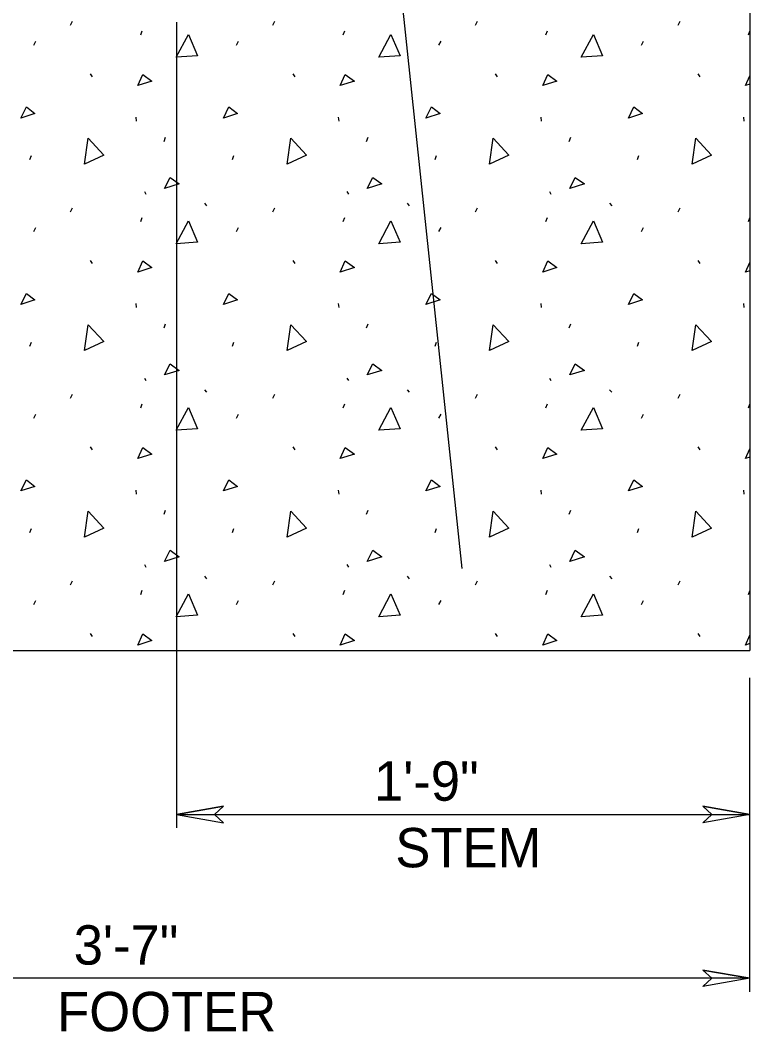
# Model space of a CAD drawing. Extents: x -26.5 to -19.2, y -3.6 to 6.6.
# Drawn here: x -23.351 to -22.237, y 0.164 to 1.707 of the extents above; entities that cross this region are included whole.
import ezdxf

# ---------------------------------------------------------------- set-up
doc = ezdxf.new("R2010")
doc.units = 0
for name, color, linetype in [('DETL-DIMS', 7, 'Continuous'), ('DETL-PATT', 7, 'Continuous'), ('Level 10', 7, 'Continuous'), ('Level 12', 7, 'Continuous'), ('SUBS-FOOT_P', 7, 'Continuous'), ('SUPR-RFRC', 7, 'Continuous')]:
    doc.layers.add(name, color=color, linetype=linetype)

msp = doc.modelspace()

# ---------------------------------------------------------------- linework, layer by layer
at = {"layer": 'DETL-DIMS'}
for p, q in [((-23.112, 0.4955), (-23.0405, 0.508)), ((-23.112, 0.4955), (-23.0405, 0.4828)), ((-23.0405, 0.508), (-23.054, 0.4955)), ((-23.054, 0.4955), (-23.0405, 0.4828)), ((-22.237, 0.4955), (-22.3085, 0.508)), ((-22.3085, 0.508), (-22.295, 0.4955)), ((-22.237, 0.4955), (-22.3085, 0.4828)), ((-22.295, 0.4955), (-22.3085, 0.4828)), ((-22.237, 0.2455), (-22.3085, 0.258)), ((-22.3085, 0.258), (-22.295, 0.2455)), ((-22.237, 0.2455), (-22.3085, 0.2328)), ((-22.295, 0.2455), (-22.3085, 0.2328))]:
    msp.add_line(p, q, dxfattribs=at)
for points in [[(-23.0405, 0.508), (-23.112, 0.4955), (-23.0405, 0.4828), (-23.054, 0.4955)], [(-22.3085, 0.508), (-22.237, 0.4955), (-22.3085, 0.4828), (-22.295, 0.4955)], [(-22.3085, 0.258), (-22.237, 0.2455), (-22.3085, 0.2328), (-22.295, 0.2455)]]:
    msp.add_lwpolyline(points, close=True, dxfattribs=at)
at = {"layer": 'DETL-PATT'}
for p, q in [((-23.2741, 1.699), (-23.271, 1.7052)), ((-22.9649, 1.699), (-22.9618, 1.7052)), ((-22.6557, 1.699), (-22.6526, 1.7052)), ((-22.3465, 1.699), (-22.3434, 1.7052)), ((-23.1666, 1.6843), (-23.1643, 1.6905)), ((-22.8575, 1.6843), (-22.8551, 1.6905)), ((-22.5483, 1.6843), (-22.546, 1.6905)), ((-22.2391, 1.6843), (-22.237, 1.69)), ((-23.3297, 1.6688), (-23.3266, 1.675)), ((-23.0205, 1.6688), (-23.0175, 1.675)), ((-22.7114, 1.6688), (-22.7083, 1.675)), ((-22.4022, 1.6688), (-22.3991, 1.675)), ((-23.2439, 1.6248), (-23.2408, 1.6202)), ((-22.9347, 1.6248), (-22.9317, 1.6202)), ((-22.6256, 1.6248), (-22.6225, 1.6202)), ((-22.3164, 1.6248), (-22.3133, 1.6202)), ((-22.2437, 1.607), (-22.237, 1.6219)), ((-22.237, 1.6092), (-22.2437, 1.607)), ((-23.1744, 1.5591), (-23.1736, 1.5529)), ((-22.8652, 1.5591), (-22.8644, 1.5529)), ((-22.556, 1.5591), (-22.5552, 1.5529)), ((-22.2468, 1.5591), (-22.2461, 1.5529)), ((-23.1311, 1.522), (-23.1288, 1.5282)), ((-22.8219, 1.522), (-22.8196, 1.5282)), ((-22.5127, 1.522), (-22.5104, 1.5282)), ((-23.3359, 1.4942), (-23.3336, 1.5003)), ((-23.0267, 1.4942), (-23.0244, 1.5003)), ((-22.7175, 1.4942), (-22.7152, 1.5003)), ((-22.4084, 1.4942), (-22.4061, 1.5003)), ((-23.1612, 1.4455), (-23.1589, 1.4416)), ((-22.852, 1.4455), (-22.8497, 1.4416)), ((-22.5429, 1.4455), (-22.5405, 1.4416)), ((-23.2741, 1.4146), (-23.271, 1.4207)), ((-23.0692, 1.4277), (-23.0661, 1.4238)), ((-22.9649, 1.4146), (-22.9618, 1.4207)), ((-22.7601, 1.4277), (-22.757, 1.4238)), ((-22.6557, 1.4146), (-22.6526, 1.4207)), ((-22.4509, 1.4277), (-22.4478, 1.4238)), ((-22.3465, 1.4146), (-22.3434, 1.4207)), ((-23.1666, 1.3999), (-23.1643, 1.406)), ((-22.8575, 1.3999), (-22.8551, 1.406)), ((-22.5483, 1.3999), (-22.546, 1.406)), ((-22.2391, 1.3999), (-22.237, 1.4055)), ((-23.3297, 1.3844), (-23.3266, 1.3906)), ((-23.0205, 1.3844), (-23.0175, 1.3906)), ((-22.7114, 1.3844), (-22.7083, 1.3906)), ((-22.4022, 1.3844), (-22.3991, 1.3906)), ((-23.2439, 1.3403), (-23.2408, 1.3357)), ((-22.9347, 1.3403), (-22.9317, 1.3357)), ((-22.6256, 1.3403), (-22.6225, 1.3357)), ((-22.3164, 1.3403), (-22.3133, 1.3357)), ((-22.2437, 1.3226), (-22.237, 1.3374)), ((-22.237, 1.3247), (-22.2437, 1.3226)), ((-23.1744, 1.2746), (-23.1736, 1.2685)), ((-22.8652, 1.2746), (-22.8644, 1.2685)), ((-22.556, 1.2746), (-22.5552, 1.2685)), ((-22.2468, 1.2746), (-22.2461, 1.2685)), ((-23.1311, 1.2375), (-23.1288, 1.2437)), ((-22.8219, 1.2375), (-22.8196, 1.2437)), ((-22.5127, 1.2375), (-22.5104, 1.2437)), ((-23.3359, 1.2097), (-23.3336, 1.2159)), ((-23.0267, 1.2097), (-23.0244, 1.2159)), ((-22.7175, 1.2097), (-22.7152, 1.2159)), ((-22.4084, 1.2097), (-22.4061, 1.2159)), ((-23.1612, 1.161), (-23.1589, 1.1572)), ((-22.852, 1.161), (-22.8497, 1.1572)), ((-22.5429, 1.161), (-22.5405, 1.1572)), ((-23.0692, 1.1432), (-23.0661, 1.1394)), ((-22.7601, 1.1432), (-22.757, 1.1394)), ((-22.4509, 1.1432), (-22.4478, 1.1394)), ((-23.2741, 1.1301), (-23.271, 1.1363)), ((-22.9649, 1.1301), (-22.9618, 1.1363)), ((-22.6557, 1.1301), (-22.6526, 1.1363)), ((-22.3465, 1.1301), (-22.3434, 1.1363)), ((-23.1666, 1.1154), (-23.1643, 1.1216)), ((-22.8575, 1.1154), (-22.8551, 1.1216)), ((-22.5483, 1.1154), (-22.546, 1.1216)), ((-22.2391, 1.1154), (-22.237, 1.1211)), ((-23.3297, 1.1), (-23.3266, 1.1061)), ((-23.0205, 1.1), (-23.0175, 1.1061)), ((-22.7114, 1.1), (-22.7083, 1.1061)), ((-22.4022, 1.1), (-22.3991, 1.1061)), ((-23.2439, 1.0559), (-23.2408, 1.0513)), ((-22.9347, 1.0559), (-22.9317, 1.0513)), ((-22.6256, 1.0559), (-22.6225, 1.0513)), ((-22.3164, 1.0559), (-22.3133, 1.0513)), ((-22.2437, 1.0381), (-22.237, 1.053)), ((-22.237, 1.0403), (-22.2437, 1.0381)), ((-23.1744, 0.9902), (-23.1736, 0.984)), ((-22.8652, 0.9902), (-22.8644, 0.984)), ((-22.556, 0.9902), (-22.5552, 0.984)), ((-22.2468, 0.9902), (-22.2461, 0.984)), ((-23.1311, 0.9531), (-23.1288, 0.9593)), ((-22.8219, 0.9531), (-22.8196, 0.9593)), ((-22.5127, 0.9531), (-22.5104, 0.9593)), ((-23.3359, 0.9253), (-23.3336, 0.9315)), ((-23.0267, 0.9253), (-23.0244, 0.9315)), ((-22.7175, 0.9253), (-22.7152, 0.9315)), ((-22.4084, 0.9253), (-22.4061, 0.9315)), ((-23.1612, 0.8766), (-23.1589, 0.8727)), ((-22.852, 0.8766), (-22.8497, 0.8727)), ((-22.5429, 0.8766), (-22.5405, 0.8727)), ((-23.2741, 0.8457), (-23.271, 0.8518)), ((-23.0692, 0.8588), (-23.0661, 0.8549)), ((-22.9649, 0.8457), (-22.9618, 0.8518)), ((-22.7601, 0.8588), (-22.757, 0.8549)), ((-22.6557, 0.8457), (-22.6526, 0.8518)), ((-22.4509, 0.8588), (-22.4478, 0.8549)), ((-22.3465, 0.8457), (-22.3434, 0.8518)), ((-23.1666, 0.831), (-23.1643, 0.8372)), ((-22.8575, 0.831), (-22.8551, 0.8372)), ((-22.5483, 0.831), (-22.546, 0.8372)), ((-22.2391, 0.831), (-22.237, 0.8366)), ((-23.3297, 0.8155), (-23.3266, 0.8217)), ((-23.0205, 0.8155), (-23.0175, 0.8217)), ((-22.7114, 0.8155), (-22.7083, 0.8217)), ((-22.4022, 0.8155), (-22.3991, 0.8217)), ((-23.2439, 0.7715), (-23.2408, 0.7668)), ((-22.9347, 0.7715), (-22.9317, 0.7668)), ((-22.6256, 0.7715), (-22.6225, 0.7668)), ((-22.3164, 0.7715), (-22.3133, 0.7668)), ((-22.2437, 0.7537), (-22.237, 0.7686)), ((-22.237, 0.7559), (-22.2437, 0.7537))]:
    msp.add_line(p, q, dxfattribs=at)
for points in [[(-23.1125, 1.6503), (-23.094, 1.6851), (-23.0801, 1.6526), (-23.1125, 1.6503)], [(-22.8033, 1.6503), (-22.7848, 1.6851), (-22.7709, 1.6526), (-22.8033, 1.6503)], [(-22.4942, 1.6503), (-22.4756, 1.6851), (-22.4617, 1.6526), (-22.4942, 1.6503)], [(-23.1713, 1.607), (-23.1635, 1.624), (-23.1496, 1.614), (-23.1713, 1.607)], [(-22.8621, 1.607), (-22.8544, 1.624), (-22.8404, 1.614), (-22.8621, 1.607)], [(-22.5529, 1.607), (-22.5452, 1.624), (-22.5313, 1.614), (-22.5529, 1.607)], [(-23.3498, 1.5575), (-23.3413, 1.5745), (-23.3282, 1.5645), (-23.3498, 1.5575)], [(-23.0406, 1.5575), (-23.0321, 1.5745), (-23.019, 1.5645), (-23.0406, 1.5575)], [(-22.7315, 1.5575), (-22.723, 1.5745), (-22.7098, 1.5645), (-22.7315, 1.5575)], [(-22.4223, 1.5575), (-22.4138, 1.5745), (-22.4006, 1.5645), (-22.4223, 1.5575)], [(-23.2524, 1.4872), (-23.247, 1.5266), (-23.2231, 1.5011), (-23.2524, 1.4872)], [(-22.9432, 1.4872), (-22.9378, 1.5266), (-22.9139, 1.5011), (-22.9432, 1.4872)], [(-22.6341, 1.4872), (-22.6287, 1.5266), (-22.6047, 1.5011), (-22.6341, 1.4872)], [(-22.3249, 1.4872), (-22.3195, 1.5266), (-22.2955, 1.5011), (-22.3249, 1.4872)], [(-23.1303, 1.4501), (-23.1218, 1.4671), (-23.1079, 1.4571), (-23.1303, 1.4501)], [(-22.8211, 1.4501), (-22.8126, 1.4671), (-22.7987, 1.4571), (-22.8211, 1.4501)], [(-22.5119, 1.4501), (-22.5034, 1.4671), (-22.4895, 1.4571), (-22.5119, 1.4501)], [(-23.1125, 1.3659), (-23.094, 1.4006), (-23.0801, 1.3682), (-23.1125, 1.3659)], [(-22.8033, 1.3659), (-22.7848, 1.4006), (-22.7709, 1.3682), (-22.8033, 1.3659)], [(-22.4942, 1.3659), (-22.4756, 1.4006), (-22.4617, 1.3682), (-22.4942, 1.3659)], [(-23.1713, 1.3226), (-23.1635, 1.3396), (-23.1496, 1.3295), (-23.1713, 1.3226)], [(-22.8621, 1.3226), (-22.8544, 1.3396), (-22.8404, 1.3295), (-22.8621, 1.3226)], [(-22.5529, 1.3226), (-22.5452, 1.3396), (-22.5313, 1.3295), (-22.5529, 1.3226)], [(-23.3498, 1.2731), (-23.3413, 1.2901), (-23.3282, 1.2801), (-23.3498, 1.2731)], [(-23.0406, 1.2731), (-23.0321, 1.2901), (-23.019, 1.2801), (-23.0406, 1.2731)], [(-22.7315, 1.2731), (-22.723, 1.2901), (-22.7098, 1.2801), (-22.7315, 1.2731)], [(-22.4223, 1.2731), (-22.4138, 1.2901), (-22.4006, 1.2801), (-22.4223, 1.2731)], [(-23.2524, 1.2028), (-23.247, 1.2422), (-23.2231, 1.2167), (-23.2524, 1.2028)], [(-22.9432, 1.2028), (-22.9378, 1.2422), (-22.9139, 1.2167), (-22.9432, 1.2028)], [(-22.6341, 1.2028), (-22.6287, 1.2422), (-22.6047, 1.2167), (-22.6341, 1.2028)], [(-22.3249, 1.2028), (-22.3195, 1.2422), (-22.2955, 1.2167), (-22.3249, 1.2028)], [(-23.1303, 1.1657), (-23.1218, 1.1827), (-23.1079, 1.1726), (-23.1303, 1.1657)], [(-22.8211, 1.1657), (-22.8126, 1.1827), (-22.7987, 1.1726), (-22.8211, 1.1657)], [(-22.5119, 1.1657), (-22.5034, 1.1827), (-22.4895, 1.1726), (-22.5119, 1.1657)], [(-23.1125, 1.0814), (-23.094, 1.1162), (-23.0801, 1.0837), (-23.1125, 1.0814)], [(-22.8033, 1.0814), (-22.7848, 1.1162), (-22.7709, 1.0837), (-22.8033, 1.0814)], [(-22.4942, 1.0814), (-22.4756, 1.1162), (-22.4617, 1.0837), (-22.4942, 1.0814)], [(-23.1713, 1.0381), (-23.1635, 1.0551), (-23.1496, 1.0451), (-23.1713, 1.0381)], [(-22.8621, 1.0381), (-22.8544, 1.0551), (-22.8404, 1.0451), (-22.8621, 1.0381)], [(-22.5529, 1.0381), (-22.5452, 1.0551), (-22.5313, 1.0451), (-22.5529, 1.0381)], [(-23.3498, 0.9887), (-23.3413, 1.0057), (-23.3282, 0.9956), (-23.3498, 0.9887)], [(-23.0406, 0.9887), (-23.0321, 1.0057), (-23.019, 0.9956), (-23.0406, 0.9887)], [(-22.7315, 0.9887), (-22.723, 1.0057), (-22.7098, 0.9956), (-22.7315, 0.9887)], [(-22.4223, 0.9887), (-22.4138, 1.0057), (-22.4006, 0.9956), (-22.4223, 0.9887)], [(-23.2524, 0.9183), (-23.247, 0.9577), (-23.2231, 0.9322), (-23.2524, 0.9183)], [(-22.9432, 0.9183), (-22.9378, 0.9577), (-22.9139, 0.9322), (-22.9432, 0.9183)], [(-22.6341, 0.9183), (-22.6287, 0.9577), (-22.6047, 0.9322), (-22.6341, 0.9183)], [(-22.3249, 0.9183), (-22.3195, 0.9577), (-22.2955, 0.9322), (-22.3249, 0.9183)], [(-23.1303, 0.8812), (-23.1218, 0.8982), (-23.1079, 0.8882), (-23.1303, 0.8812)], [(-22.8211, 0.8812), (-22.8126, 0.8982), (-22.7987, 0.8882), (-22.8211, 0.8812)], [(-22.5119, 0.8812), (-22.5034, 0.8982), (-22.4895, 0.8882), (-22.5119, 0.8812)], [(-23.1125, 0.797), (-23.094, 0.8318), (-23.0801, 0.7993), (-23.1125, 0.797)], [(-22.8033, 0.797), (-22.7848, 0.8318), (-22.7709, 0.7993), (-22.8033, 0.797)], [(-22.4942, 0.797), (-22.4756, 0.8318), (-22.4617, 0.7993), (-22.4942, 0.797)], [(-23.1713, 0.7537), (-23.1635, 0.7707), (-23.1496, 0.7606), (-23.1713, 0.7537)], [(-22.8621, 0.7537), (-22.8544, 0.7707), (-22.8404, 0.7606), (-22.8621, 0.7537)], [(-22.5529, 0.7537), (-22.5452, 0.7707), (-22.5313, 0.7606), (-22.5529, 0.7537)]]:
    msp.add_lwpolyline(points, dxfattribs=at)
at = {"layer": 'Level 10'}
for p, q in [((-23.112, 1.7039), (-23.112, 0.4747)), ((-22.237, 0.2247), (-22.237, 0.7039)), ((-23.112, 0.4955), (-22.237, 0.4955)), ((-22.237, 0.2455), (-24.0286, 0.2455))]:
    msp.add_line(p, q, dxfattribs=at)
at = {"layer": 'SUBS-FOOT_P'}
for p in [(-22.237, 1.7455), (-24.0286, 0.7455)]:
    msp.add_line(p, (-22.237, 0.7455), dxfattribs=at)
at = {"layer": 'SUPR-RFRC'}
msp.add_line((-23.0958, 4.8436), (-22.6767, 0.8705), dxfattribs=at)

# ---------------------------------------------------------------- texts
at = {"layer": 'Level 12'}
for s, p in [('1\'-9"', (-22.8106, 0.5163)), ('STEM', (-22.7781, 0.4147)), ('3\'-7"', (-23.269, 0.2663)), ('FOOTER', (-23.2943, 0.1647))]:
    msp.add_text(s, height=0.06001, dxfattribs=at).set_placement(p)

doc.saveas('drawing.dxf')
